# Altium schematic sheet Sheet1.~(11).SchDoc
size A4; SheetNumber: 1; SheetTotal: 1
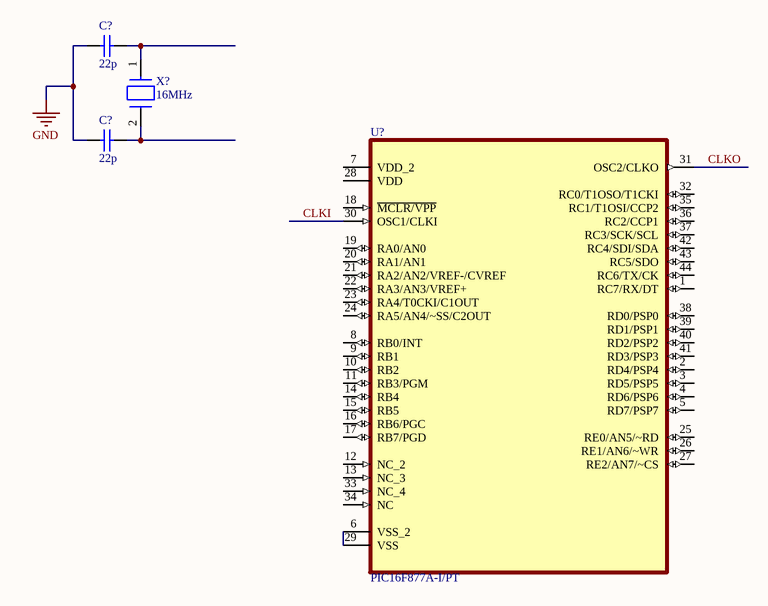
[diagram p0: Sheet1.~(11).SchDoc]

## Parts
(Parts that share a designator on the sheet are numbered #1, #2 ... from top to bottom, then left to right.)
C?#1  22p  [CAPC2013X94X50LL25T25]
C?#2  22p  [CAPC2013X94X50LL25T25]
U?  PIC16F877A-I/PT  [TQFP-44]
X?  16MHz  [FP-ABM7-MFG]

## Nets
GND: C?#1.1 C?#2.1
CLKI: U?.30(OSC1/CLKI)
CLKO: U?.31(OSC2/CLKO)
NetC?#1_2: C?#1.2 X?.1
NetC?#2_2: C?#2.2 X?.2
NetU?_6: U?.6(VSS_2) U?.29(VSS)

Not connected (* = marked no-connect by the designer): U? 1(RC7/RX/DT) 2(RD4/PSP4) 3(RD5/PSP5) 4(RD6/PSP6) 5(RD7/PSP7) 7(VDD_2) 8(RB0/INT) 9(RB1) 10(RB2) 11(RB3/PGM) 12(NC_2) 13(NC_3) 14(RB4) 15(RB5) 16(RB6/PGC) 17(RB7/PGD) 18(~{MCLR/VPP}) 19(RA0/AN0) 20(RA1/AN1) 21(RA2/AN2/VREF-/CVREF) 22(RA3/AN3/VREF+) 23(RA4/T0CKI/C1OUT) 24(RA5/AN4/~SS/C2OUT) 25(RE0/AN5/~RD) 26(RE1/AN6/~WR) 27(RE2/AN7/~CS) 28(VDD) 32(RC0/T1OSO/T1CKI) 33(NC_4) 34(NC) 35(RC1/T1OSI/CCP2) 36(RC2/CCP1) 37(RC3/SCK/SCL) 38(RD0/PSP0) 39(RD1/PSP1) 40(RD2/PSP2) 41(RD3/PSP3) 42(RC4/SDI/SDA) 43(RC5/SDO) 44(RC6/TX/CK)

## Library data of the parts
C?#1 C?#2 = LD051C104KAB2A: Cap Ceramic 0.1uF 100V X7R 10% SMD 0805 125°C Embossed T/R; Manufacturer: Kyocera AVX; Value: 100nF
U? = PIC16F877A-I/PT: PIC16F877A Microcontroller IC 8-Bit 20MHz 14KB _8K x 14_ FLASH 44-TQFP _10x10_; MF: Microchip
X? = ABM7-16.000MHZ-4-T: Crystal 16MHz ±30ppm (Tol) ±50ppm (Stability) 18pF FUND 50Ohm 2-Pin Mini-CSMD T/R; Manufacturer: Abracon; ESR (Equivalent Series Resistance): 50R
